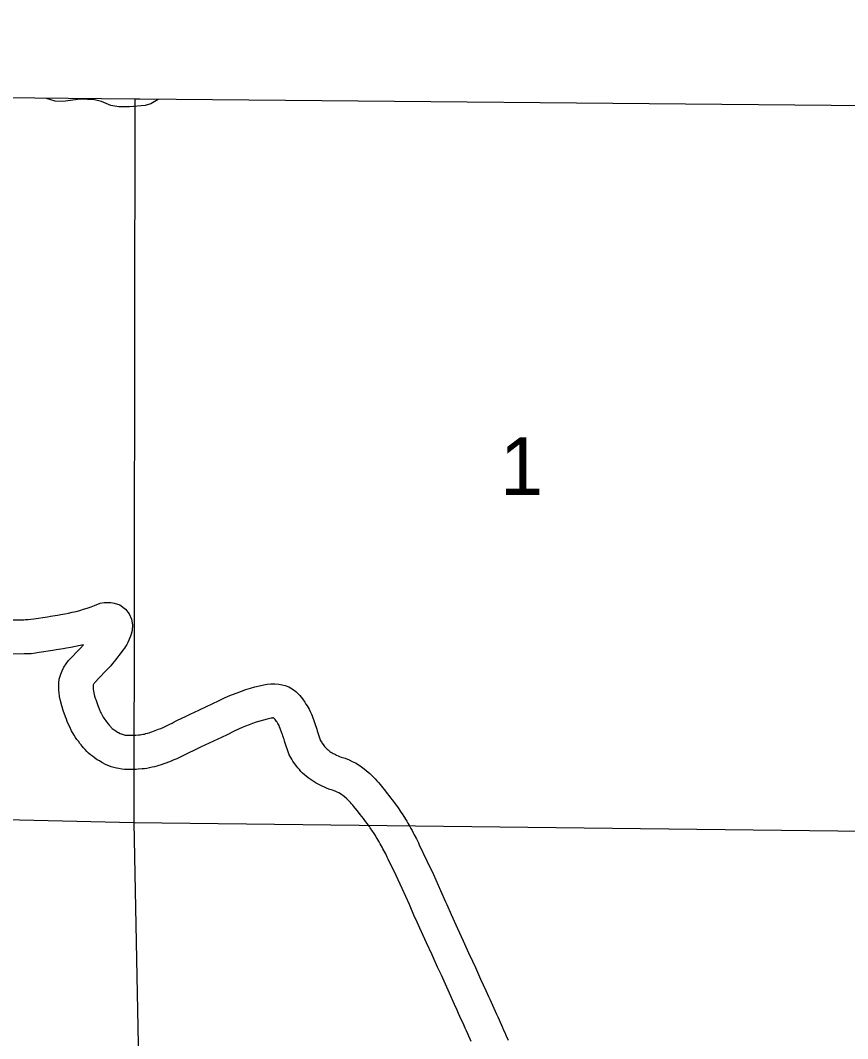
# Model space of a CAD drawing. Extents: x -19 to 366, y -4 to 359.
# Drawn here: x 138.218 to 139.362, y 202.778 to 204.187 of the extents above; entities that cross this region are included whole.
import ezdxf

# ---------------------------------------------------------------- set-up
doc = ezdxf.new("R2010")
doc.units = 0
for name, color, linetype in [('R_Alt Surface', 7, 'Continuous'), ('R_Axis Annot', 7, 'Continuous'), ('R_Contour Annot', 7, 'Continuous'), ('R_Temp Easement', 7, 'Continuous'), ('Sheet Fence', 7, 'Continuous')]:
    doc.layers.add(name, color=color, linetype=linetype)

msp = doc.modelspace()

# ---------------------------------------------------------------- linework, layer by layer
at = {"layer": 'R_Alt Surface'}
msp.add_lwpolyline([(139.3896, 204.0685), (138.383, 204.0778), (138.3761, 204.0776), (137.7294, 204.084)], dxfattribs=at)
at = {"layer": 'R_Axis Annot'}
for points in [[(138.3761, 204.0776), (138.3744, 203.0767)], [(137.3855, 203.0998), (138.3744, 203.0767)], [(138.3744, 203.0767), (139.3874, 203.0648)], [(138.3744, 203.0767), (138.3811, 202.7458)]]:
    msp.add_lwpolyline(points, dxfattribs=at)
at = {"layer": 'R_Contour Annot'}
for p, q in [((138.2759, 203.235), (138.2758, 203.2354)), ((138.5816, 203.194), (138.5816, 203.1939))]:
    msp.add_line(p, q, dxfattribs=at)
for points in [[(138.207, 203.3572), (138.2222, 203.3573), (138.2248, 203.3574), (138.2274, 203.3574), (138.2285, 203.3574), (138.2318, 203.3579), (138.2363, 203.3585), (138.2549, 203.3614), (138.2594, 203.3621), (138.2687, 203.3636), (138.2733, 203.3644), (138.2789, 203.3654), (138.2841, 203.3664), (138.2893, 203.3676), (138.2946, 203.3688), (138.2998, 203.3702), (138.305, 203.3717), (138.31, 203.3733), (138.3153, 203.3751), (138.3203, 203.3769), (138.3279, 203.38), (138.3336, 203.3809), (138.3378, 203.3811), (138.3425, 203.381), (138.3474, 203.3802), (138.3552, 203.3779), (138.363, 203.3719), (138.368, 203.3655), (138.3712, 203.3582), (138.3727, 203.3504), (138.3723, 203.3425), (138.3709, 203.3375), (138.3699, 203.3344), (138.3687, 203.3314), (138.3677, 203.3289), (138.3662, 203.3258), (138.3646, 203.3229), (138.3631, 203.3203), (138.3614, 203.3178), (138.3594, 203.3151), (138.3582, 203.3136), (138.3567, 203.3114), (138.3544, 203.3083), (138.3521, 203.3053), (138.3497, 203.3022), (138.345, 203.2965), (138.3425, 203.2936), (138.3399, 203.2907), (138.3349, 203.2855), (138.32, 203.2698), (138.3194, 203.2691), (138.3189, 203.2683), (138.3184, 203.2673), (138.3181, 203.2664), (138.3181, 203.2664), (138.3181, 203.2652), (138.3182, 203.2621), (138.3183, 203.261), (138.3186, 203.2583), (138.319, 203.2562), (138.3203, 203.2517), (138.3211, 203.2489)], [(138.2758, 203.2354), (138.2749, 203.2383), (138.2729, 203.2452), (138.2718, 203.2511), (138.2711, 203.2565), (138.2709, 203.2594), (138.2707, 203.2642), (138.2707, 203.2671), (138.2708, 203.2699), (138.2711, 203.2752), (138.2733, 203.2819), (138.2752, 203.2867), (138.2777, 203.2916), (138.2807, 203.2964), (138.2841, 203.3008), (138.3006, 203.3181), (138.3049, 203.3226), (138.3001, 203.3214), (138.2938, 203.32), (138.2873, 203.3188), (138.2812, 203.3177), (138.2765, 203.3169), (138.2671, 203.3154), (138.2623, 203.3146), (138.2434, 203.3117), (138.2386, 203.311), (138.2325, 203.3102), (138.2283, 203.31), (138.2257, 203.31), (138.223, 203.3099), (138.2067, 203.3098)], [(138.3211, 203.2489), (138.3219, 203.2467), (138.3246, 203.2388), (138.3255, 203.2364), (138.3265, 203.2339), (138.3273, 203.2317), (138.3281, 203.23), (138.3291, 203.2279), (138.33, 203.2262), (138.3321, 203.2225), (138.3331, 203.2209), (138.3344, 203.2192), (138.3356, 203.2175), (138.3369, 203.2158), (138.3388, 203.2134), (138.3403, 203.2115), (138.3412, 203.2103), (138.3421, 203.2093), (138.3429, 203.2085), (138.3438, 203.2076), (138.3447, 203.2069), (138.3459, 203.2059), (138.3472, 203.2049), (138.3482, 203.2043), (138.3499, 203.2032), (138.3521, 203.2018), (138.3531, 203.2012), (138.3558, 203.1998), (138.357, 203.1993), (138.3585, 203.1988), (138.3599, 203.1984), (138.3612, 203.198), (138.3626, 203.1977), (138.3637, 203.1975), (138.3646, 203.1975), (138.3662, 203.1974), (138.3701, 203.1973), (138.3717, 203.1973), (138.3756, 203.1974), (138.3773, 203.1975), (138.3811, 203.1978), (138.3831, 203.1981), (138.3853, 203.1984), (138.3873, 203.1987), (138.3891, 203.1991), (138.3913, 203.1996), (138.3934, 203.2002), (138.3956, 203.2008), (138.3977, 203.2015), (138.3995, 203.2021), (138.4016, 203.203), (138.4086, 203.2057), (138.4117, 203.2069), (138.4149, 203.2083), (138.418, 203.2097), (138.4244, 203.2127), (138.4275, 203.2142), (138.4304, 203.2158), (138.4342, 203.2178), (138.4467, 203.2236), (138.4526, 203.2264), (138.4584, 203.2292), (138.4644, 203.2319), (138.4761, 203.2376), (138.4819, 203.2404), (138.4937, 203.246), (138.4992, 203.2487), (138.5051, 203.2514), (138.5112, 203.254), (138.5173, 203.2563), (138.5234, 203.2585), (138.5296, 203.2606), (138.5357, 203.2624), (138.542, 203.2642), (138.5484, 203.2658), (138.5546, 203.2672), (138.5589, 203.268), (138.5641, 203.2686), (138.5696, 203.2687), (138.5752, 203.2681), (138.5796, 203.2673), (138.5841, 203.2663), (138.5891, 203.2642), (138.5938, 203.2617), (138.5986, 203.2581), (138.6021, 203.2546), (138.6041, 203.2522), (138.606, 203.25), (138.6078, 203.2476), (138.611, 203.2432), (138.6127, 203.2406), (138.6142, 203.2382), (138.617, 203.2335), (138.6187, 203.2301), (138.6201, 203.2268), (138.6212, 203.2241), (138.624, 203.2164), (138.6251, 203.2135), (138.6259, 203.2108), (138.6267, 203.2084)], [(138.5816, 203.1939), (138.5808, 203.1964), (138.5801, 203.1985), (138.5795, 203.2003), (138.577, 203.2069), (138.5762, 203.2089), (138.5757, 203.2102), (138.5754, 203.2109), (138.5736, 203.2138), (138.5727, 203.2153), (138.572, 203.2164), (138.57, 203.2191), (138.5691, 203.2203), (138.5683, 203.2212), (138.5682, 203.2212), (138.5676, 203.2213), (138.567, 203.2213), (138.5662, 203.2212), (138.5644, 203.2209), (138.5591, 203.2196), (138.5541, 203.2184), (138.549, 203.217), (138.5439, 203.2155), (138.5389, 203.2138), (138.5339, 203.212), (138.529, 203.2101), (138.5242, 203.208), (138.5194, 203.2058), (138.5143, 203.2034), (138.5025, 203.1977), (138.4966, 203.1949), (138.4846, 203.1892), (138.4787, 203.1864), (138.4728, 203.1835), (138.4667, 203.1807), (138.4555, 203.1755), (138.4526, 203.1739), (138.4488, 203.172), (138.445, 203.1701), (138.4378, 203.1667), (138.4339, 203.1649), (138.43, 203.1633), (138.4261, 203.1617), (138.4189, 203.1589), (138.416, 203.1577), (138.4125, 203.1565), (138.4093, 203.1555), (138.4061, 203.1546), (138.403, 203.1537), (138.3997, 203.153), (138.3962, 203.1522), (138.3927, 203.1516), (138.3894, 203.1511), (138.3859, 203.1507), (138.3807, 203.1503), (138.3777, 203.1501), (138.3725, 203.1499), (138.3695, 203.1499), (138.3644, 203.1501), (138.3614, 203.1502), (138.3577, 203.1505), (138.3539, 203.1512), (138.3503, 203.1519), (138.3467, 203.1529), (138.3432, 203.1539), (138.34, 203.1552), (138.3364, 203.1566), (138.3301, 203.1597), (138.3268, 203.1618), (138.3248, 203.1631), (138.3225, 203.1645), (138.3196, 203.1665), (138.3172, 203.1683), (138.3146, 203.1703), (138.312, 203.1726), (138.3095, 203.1749), (138.307, 203.1775), (138.3049, 203.1799), (138.3029, 203.1824), (138.3015, 203.1842), (138.2999, 203.1862), (138.2978, 203.189), (138.2958, 203.1917), (138.2938, 203.1945), (138.2918, 203.1977), (138.2883, 203.2037), (138.2867, 203.2069), (138.2853, 203.2098), (138.2837, 203.2132), (138.2824, 203.2166), (138.2812, 203.2196), (138.28, 203.2229), (138.2769, 203.2318), (138.2759, 203.235)], [(138.6267, 203.2084), (138.6275, 203.2057), (138.6282, 203.2036), (138.633, 203.1897), (138.6331, 203.1897), (138.634, 203.1881), (138.6347, 203.1869), (138.6364, 203.1844), (138.6372, 203.1834), (138.6383, 203.1819), (138.6392, 203.1808), (138.6401, 203.1799), (138.6409, 203.1791), (138.6419, 203.1782), (138.6432, 203.1771), (138.6446, 203.1759), (138.6457, 203.1751), (138.6471, 203.1742), (138.649, 203.173), (138.6501, 203.1723), (138.6517, 203.1715), (138.6533, 203.1706), (138.655, 203.1698), (138.6573, 203.1687), (138.6592, 203.1679), (138.6613, 203.1672), (138.6632, 203.1665), (138.6671, 203.1655), (138.6725, 203.1632), (138.6767, 203.1612), (138.681, 203.159), (138.6849, 203.1567), (138.6896, 203.1538), (138.6931, 203.1511), (138.6959, 203.1488), (138.701, 203.1443), (138.7037, 203.1418), (138.7061, 203.1393), (138.7084, 203.137), (138.7108, 203.1344), (138.7131, 203.1318), (138.7154, 203.1291), (138.7227, 203.1199), (138.725, 203.117), (138.7274, 203.114), (138.7297, 203.1109), (138.7319, 203.108), (138.7391, 203.0985), (138.741, 203.0957), (138.7441, 203.091), (138.7458, 203.0885), (138.7489, 203.0835), (138.7504, 203.0811), (138.752, 203.0784), (138.7535, 203.0758), (138.7548, 203.0736), (138.7563, 203.0711), (138.7579, 203.0684), (138.7595, 203.0654), (138.7611, 203.0625), (138.7625, 203.0598), (138.7654, 203.0542), (138.7668, 203.0512), (138.7682, 203.0483), (138.7693, 203.0458), (138.7801, 203.0235), (138.7889, 203.0048), (138.7989, 202.9824), (138.8058, 202.9667), (138.8077, 202.9632), (138.8135, 202.9495), (138.8225, 202.9299), (138.8303, 202.9131), (138.8377, 202.8962), (138.8431, 202.8849), (138.847, 202.8759), (138.8541, 202.8599), (138.8614, 202.8443), (138.8652, 202.836), (138.8669, 202.832), (138.8688, 202.828), (138.8743, 202.8157), (138.8762, 202.8116), (138.878, 202.8076), (138.8798, 202.8034), (138.8845, 202.7928), (138.8861, 202.7893), (138.8877, 202.7858), (138.8892, 202.7824), (138.8925, 202.7753)], [(138.8413, 202.7735), (138.8366, 202.7842), (138.8348, 202.7881), (138.833, 202.7922), (138.8311, 202.7964), (138.8257, 202.8083), (138.8238, 202.8125), (138.8219, 202.8167), (138.8184, 202.8246), (138.8111, 202.8403), (138.8037, 202.8569), (138.8, 202.8654), (138.7947, 202.8765), (138.7872, 202.8935), (138.7795, 202.91), (138.7702, 202.9303), (138.7648, 202.9429), (138.763, 202.9463), (138.7557, 202.9632), (138.7458, 202.9851), (138.7374, 203.0031), (138.7264, 203.0257), (138.7251, 203.0286), (138.724, 203.0309), (138.723, 203.0331), (138.7205, 203.038), (138.7192, 203.0404), (138.7179, 203.0427), (138.7168, 203.0449), (138.7154, 203.0471), (138.714, 203.0497), (138.7125, 203.0522), (138.7113, 203.0543), (138.71, 203.0563), (138.7087, 203.0585), (138.706, 203.0627), (138.7046, 203.0648), (138.7017, 203.0693), (138.7006, 203.0709), (138.6943, 203.0792), (138.6921, 203.0821), (138.6899, 203.085), (138.6877, 203.0878), (138.6854, 203.0908), (138.6789, 203.099), (138.6774, 203.1007), (138.6757, 203.1026), (138.6741, 203.1043), (138.6724, 203.1061), (138.6706, 203.1078), (138.6691, 203.1093), (138.6653, 203.1127), (138.6636, 203.114), (138.6624, 203.115), (138.6606, 203.1161), (138.6582, 203.1175), (138.6557, 203.1188), (138.6531, 203.12), (138.6516, 203.1206), (138.6496, 203.1212), (138.6456, 203.1225), (138.6419, 203.1238), (138.6382, 203.1254), (138.6349, 203.1269), (138.6321, 203.1283), (138.6294, 203.1297), (138.6266, 203.1312), (138.6242, 203.1327), (138.6212, 203.1346), (138.6185, 203.1364), (138.6156, 203.1385), (138.6131, 203.1406), (138.6107, 203.1426), (138.608, 203.145), (138.6057, 203.1474), (138.6035, 203.1498), (138.6016, 203.1521), (138.5999, 203.1541), (138.598, 203.1566), (138.5946, 203.1616), (138.5931, 203.1643), (138.5918, 203.1665), (138.5896, 203.1705), (138.5831, 203.1891), (138.5823, 203.1919), (138.5816, 203.194)]]:
    msp.add_lwpolyline(points, dxfattribs=at)
at = {"layer": 'R_Temp Easement'}
msp.add_lwpolyline([(138.4084, 204.0775), (138.3982, 204.0714), (138.3902, 204.0691), (138.3683, 204.0672), (138.3536, 204.0672), (138.3426, 204.0691), (138.3297, 204.0744), (138.3203, 204.077), (138.3006, 204.0778), (138.2761, 204.0747), (138.2655, 204.0751), (138.2538, 204.0788)], dxfattribs=at)
at = {"layer": 'Sheet Fence'}
for points in [[(146.7783, 1.697), (146.5788, 10.3131), (146.3785, 18.9294), (146.1776, 27.5458), (145.9759, 36.1624), (145.7736, 44.7791), (145.5705, 53.396), (145.3668, 62.013), (145.1624, 70.6301), (144.9572, 79.2474), (144.7514, 87.8648), (144.5449, 96.4823), (144.3377, 105.1), (144.1299, 113.7179), (143.9213, 122.3359), (143.712, 130.954), (143.5021, 139.5723), (143.2915, 148.1907), (143.0802, 156.8092), (142.8682, 165.4279), (142.6555, 174.0468), (142.4422, 182.6658), (142.2282, 191.2849), (142.0135, 199.9042), (141.7981, 208.5236), (141.582, 217.1432), (141.3653, 225.7629), (141.1479, 234.3828), (140.9298, 243.0028), (140.711, 251.623), (140.4916, 260.2433), (140.2715, 268.8638), (140.0508, 277.4844), (139.8293, 286.1051), (139.6072, 294.726), (139.3845, 303.3471), (139.161, 311.9683), (138.937, 320.5896), (138.7122, 329.2111), (138.4868, 337.8328), (138.2607, 346.4546)], [(139.4406, 1.5315), (139.2511, 10.1473), (139.0608, 18.7633), (138.8699, 27.3793), (138.6784, 35.9956), (138.4861, 44.6119), (138.2932, 53.2285), (138.0997, 61.8451), (137.9055, 70.4619), (137.7106, 79.0789), (137.5151, 87.6959), (137.319, 96.3132), (137.1221, 104.9306), (136.9247, 113.5481), (136.7265, 122.1658), (136.5278, 130.7836), (136.3283, 139.4016), (136.1282, 148.0197), (135.9275, 156.6379), (135.7261, 165.2564), (135.5241, 173.8749), (135.3214, 182.4936), (135.1181, 191.1125), (134.9141, 199.7315), (134.7095, 208.3506), (134.5043, 216.9699), (134.2984, 225.5894), (134.0919, 234.209), (133.8847, 242.8288), (133.6769, 251.4487), (133.4685, 260.0687), (133.2594, 268.6889), (133.0497, 277.3093), (132.8393, 285.9298), (132.6283, 294.5504), (132.4167, 303.1713), (132.2044, 311.7922), (131.9916, 320.4133), (131.778, 329.0346), (131.5639, 337.656), (131.3491, 346.2776)], [(0, 198.1326), (7.1014, 198.137), (14.2028, 198.1503), (21.3042, 198.1724), (28.4055, 198.2034), (35.5068, 198.2433), (42.6081, 198.292), (49.7092, 198.3496), (56.8103, 198.4161), (63.9113, 198.4913), (71.0123, 198.5755), (78.1131, 198.6685), (85.2137, 198.7704), (92.3143, 198.8811), (99.4147, 199.0007), (106.5149, 199.1291), (113.615, 199.2664), (120.7149, 199.4126), (127.8146, 199.5676), (134.9141, 199.7315), (142.0135, 199.9042), (149.1125, 200.0858), (156.2114, 200.2762), (163.31, 200.4755), (170.4084, 200.6837), (177.5065, 200.9007), (184.6043, 201.1265), (191.7018, 201.3612), (198.799, 201.6048), (205.896, 201.8572), (212.9926, 202.1185), (220.0888, 202.3886), (227.1848, 202.6676), (234.2803, 202.9554), (241.3755, 203.2521), (248.4704, 203.5576), (255.5648, 203.872), (262.6589, 204.1952), (269.7525, 204.5273), (276.8457, 204.8682), (283.9385, 205.218), (291.0309, 205.5766), (298.1228, 205.9441), (305.2142, 206.3204), (312.3051, 206.7056), (319.3956, 207.0996), (326.4856, 207.5024), (333.5751, 207.9141), (340.664, 208.3347)]]:
    msp.add_spline(points, degree=3, dxfattribs=at)

# ---------------------------------------------------------------- texts
at = {"layer": 'R_Axis Annot'}
msp.add_text('1', height=0.08, dxfattribs=at).set_placement((138.8811, 203.5298))

doc.saveas('drawing.dxf')
